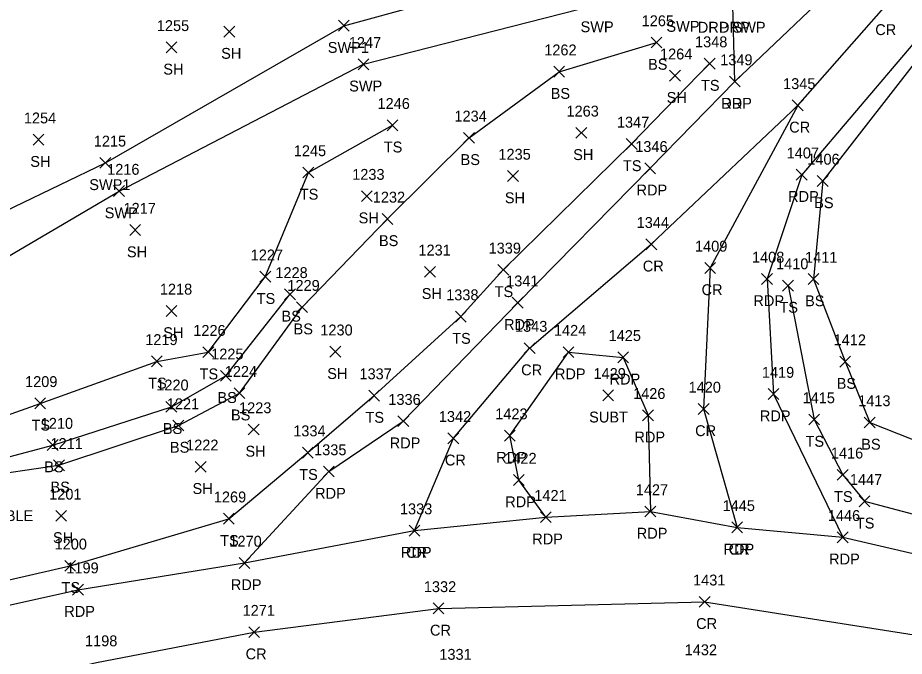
# Model space of a CAD drawing. Extents: x 1586965 to 1590952, y 716317 to 720029.
# Drawn here: x 1587644.2 to 1587807.3, y 719836.9 to 719954.3 of the extents above; entities that cross this region are included whole.
import ezdxf

# ---------------------------------------------------------------- set-up
doc = ezdxf.new("R2010")
doc.units = 0
for name, color, linetype in [('D_C', 7, 'Continuous'), ('L_A', 7, 'Continuous'), ('L_I', 7, 'Continuous'), ('L_TIC', 7, 'Continuous'), ('LELB', 7, 'Continuous'), ('P_A', 7, 'Continuous'), ('P_I', 7, 'Continuous'), ('P_TIC', 7, 'Continuous'), ('PET', 7, 'Continuous'), ('PRC', 7, 'Continuous'), ('R_A', 7, 'Continuous'), ('R_I', 7, 'Continuous'), ('R_TIC', 7, 'Continuous'), ('RDP', 7, 'Continuous'), ('RSW', 7, 'Continuous'), ('U_A', 7, 'Continuous'), ('U_I', 7, 'Continuous'), ('U_TIC', 7, 'Continuous')]:
    doc.layers.add(name, color=color, linetype=linetype)

msp = doc.modelspace()

# ---------------------------------------------------------------- linework, layer by layer
at = {"layer": 'L_TIC'}
for points in [[(1587682.13, 719950.75), (1587684.13, 719952.75)], [(1587684.13, 719950.75), (1587682.13, 719952.75)], [(1587671.48, 719947.85), (1587673.48, 719949.85)], [(1587673.48, 719947.85), (1587671.48, 719949.85)], [(1587760.72, 719948.74), (1587762.72, 719950.74)], [(1587762.72, 719948.74), (1587760.72, 719950.74)], [(1587770.49, 719944.87), (1587772.49, 719946.87)], [(1587772.49, 719944.87), (1587770.49, 719946.87)], [(1587742.8, 719943.38), (1587744.8, 719945.38)], [(1587744.8, 719943.38), (1587742.8, 719945.38)], [(1587764.1, 719942.63), (1587766.1, 719944.63)], [(1587766.1, 719942.63), (1587764.1, 719944.63)], [(1587712.13, 719933.53), (1587714.13, 719935.53)], [(1587714.13, 719933.53), (1587712.13, 719935.53)], [(1587647.01, 719930.87), (1587649.01, 719932.87)], [(1587649.01, 719930.87), (1587647.01, 719932.87)], [(1587726.23, 719931.21), (1587728.23, 719933.21)], [(1587728.23, 719931.21), (1587726.23, 719933.21)], [(1587746.89, 719932.13), (1587748.89, 719934.13)], [(1587748.89, 719932.13), (1587746.89, 719934.13)], [(1587756.13, 719930.09), (1587758.13, 719932.09)], [(1587758.13, 719930.09), (1587756.13, 719932.09)], [(1587696.67, 719924.84), (1587698.67, 719926.84)], [(1587698.67, 719924.84), (1587696.67, 719926.84)], [(1587734.32, 719924.19), (1587736.32, 719926.19)], [(1587736.32, 719924.19), (1587734.32, 719926.19)], [(1587791.29, 719923.28), (1587793.29, 719925.28)], [(1587793.29, 719923.28), (1587791.29, 719925.28)], [(1587707.43, 719920.49), (1587709.43, 719922.49)], [(1587709.43, 719920.49), (1587707.43, 719922.49)], [(1587711.21, 719916.3), (1587713.21, 719918.3)], [(1587713.21, 719916.3), (1587711.21, 719918.3)], [(1587664.79, 719914.25), (1587666.79, 719916.25)], [(1587666.79, 719914.25), (1587664.79, 719916.25)], [(1587719.04, 719906.57), (1587721.04, 719908.57)], [(1587721.04, 719906.57), (1587719.04, 719908.57)], [(1587732.52, 719906.93), (1587734.52, 719908.93)], [(1587734.52, 719906.93), (1587732.52, 719908.93)], [(1587688.74, 719905.67), (1587690.74, 719907.67)], [(1587690.74, 719905.67), (1587688.74, 719907.67)], [(1587789.61, 719905.24), (1587791.61, 719907.24)], [(1587791.61, 719905.24), (1587789.61, 719907.24)], [(1587784.92, 719904.04), (1587786.92, 719906.04)], [(1587786.92, 719904.04), (1587784.92, 719906.04)], [(1587693.28, 719902.42), (1587695.28, 719904.42)], [(1587695.28, 719902.42), (1587693.28, 719904.42)], [(1587695.5, 719900.07), (1587697.5, 719902.07)], [(1587697.5, 719900.07), (1587695.5, 719902.07)], [(1587671.47, 719899.38), (1587673.47, 719901.38)], [(1587673.47, 719899.38), (1587671.47, 719901.38)], [(1587724.71, 719898.33), (1587726.71, 719900.33)], [(1587726.71, 719898.33), (1587724.71, 719900.33)], [(1587678.24, 719891.79), (1587680.24, 719893.79)], [(1587680.24, 719891.79), (1587678.24, 719893.79)], [(1587701.64, 719891.87), (1587703.64, 719893.87)], [(1587703.64, 719891.87), (1587701.64, 719893.87)], [(1587668.78, 719890.1), (1587670.78, 719892.1)], [(1587670.78, 719890.1), (1587668.78, 719892.1)], [(1587795.42, 719890.05), (1587797.42, 719892.05)], [(1587797.42, 719890.05), (1587795.42, 719892.05)], [(1587681.48, 719887.45), (1587683.48, 719889.45)], [(1587683.48, 719887.45), (1587681.48, 719889.45)], [(1587683.98, 719884.25), (1587685.98, 719886.25)], [(1587685.98, 719884.25), (1587683.98, 719886.25)], [(1587708.76, 719883.81), (1587710.76, 719885.81)], [(1587710.76, 719883.81), (1587708.76, 719885.81)], [(1587647.32, 719882.38), (1587649.32, 719884.38)], [(1587649.32, 719882.38), (1587647.32, 719884.38)], [(1587671.46, 719881.75), (1587673.46, 719883.75)], [(1587673.46, 719881.75), (1587671.46, 719883.75)], [(1587789.72, 719879.4), (1587791.72, 719881.4)], [(1587791.72, 719879.4), (1587789.72, 719881.4)], [(1587799.94, 719878.86), (1587801.94, 719880.86)], [(1587801.94, 719878.86), (1587799.94, 719880.86)], [(1587672.75, 719878.3), (1587674.75, 719880.3)], [(1587674.75, 719878.3), (1587672.75, 719880.3)], [(1587686.61, 719877.57), (1587688.61, 719879.57)], [(1587688.61, 719877.57), (1587686.61, 719879.57)], [(1587649.63, 719874.7), (1587651.63, 719876.7)], [(1587651.63, 719874.7), (1587649.63, 719876.7)], [(1587696.57, 719873.31), (1587698.57, 719875.31)], [(1587698.57, 719873.31), (1587696.57, 719875.31)], [(1587650.78, 719870.98), (1587652.78, 719872.98)], [(1587652.78, 719870.98), (1587650.78, 719872.98)], [(1587676.86, 719870.71), (1587678.86, 719872.71)], [(1587678.86, 719870.71), (1587676.86, 719872.71)], [(1587794.97, 719869.23), (1587796.97, 719871.23)], [(1587796.97, 719869.23), (1587794.97, 719871.23)], [(1587798.98, 719864.36), (1587800.98, 719866.36)], [(1587800.98, 719864.36), (1587798.98, 719866.36)], [(1587651.18, 719861.68), (1587653.18, 719863.68)], [(1587653.18, 719861.68), (1587651.18, 719863.68)], [(1587682.02, 719861.16), (1587684.02, 719863.16)], [(1587684.02, 719861.16), (1587682.02, 719863.16)], [(1587652.83, 719852.5), (1587654.83, 719854.5)], [(1587654.83, 719852.5), (1587652.83, 719854.5)]]:
    msp.add_lwpolyline(points, dxfattribs=at)
at = {"layer": 'LELB'}
for points in [[(1587348.34, 719750.32), (1587376.14, 719764.57), (1587411.23, 719784.15), (1587458.35, 719804.18), (1587473.61, 719812.83), (1587489.06, 719812.38), (1587530.46, 719833.31), (1587544.39, 719838.73), (1587578.28, 719845.78), (1587610.35, 719855.43), (1587636.65, 719869.8), (1587651.78, 719871.98), (1587673.75, 719879.3), (1587684.98, 719885.25), (1587696.5, 719901.07), (1587712.21, 719917.3), (1587727.23, 719932.21), (1587743.8, 719944.38), (1587761.72, 719949.74)], [(1587348.34, 719750.32), (1587376.14, 719764.57), (1587411.23, 719784.15), (1587458.35, 719804.18), (1587473.61, 719812.83), (1587489.06, 719812.38), (1587530.46, 719833.31), (1587544.39, 719838.73), (1587578.28, 719845.78), (1587610.35, 719855.43), (1587636.65, 719869.8), (1587651.78, 719871.98), (1587673.75, 719879.3), (1587684.98, 719885.25), (1587696.5, 719901.07), (1587712.21, 719917.3), (1587727.23, 719932.21), (1587743.8, 719944.38), (1587761.72, 719949.74)], [(1587811.93, 719949.52), (1587792.29, 719924.28), (1587790.61, 719906.24), (1587796.42, 719891.05), (1587800.94, 719879.86), (1587824.09, 719870.75), (1587863.89, 719860.75), (1587885.59, 719851.77), (1587915.12, 719838.63), (1587948, 719820.59), (1587984.49, 719804.22), (1588019.19, 719787.78), (1588025.35, 719786.55), (1588029.77, 719787.48), (1588038.8, 719793.55), (1588050.21, 719818.02), (1588057.55, 719835.32), (1588061.37, 719857.52)], [(1587811.93, 719949.52), (1587792.29, 719924.28), (1587790.61, 719906.24), (1587796.42, 719891.05), (1587800.94, 719879.86), (1587824.09, 719870.75), (1587863.89, 719860.75), (1587885.59, 719851.77), (1587915.12, 719838.63), (1587948, 719820.59), (1587984.49, 719804.22), (1588019.19, 719787.78), (1588025.35, 719786.55), (1588029.77, 719787.48), (1588038.8, 719793.55), (1588050.21, 719818.02), (1588057.55, 719835.32), (1588061.37, 719857.52)], [(1587377.37, 719757.84), (1587414.05, 719779.22), (1587461.92, 719797.99), (1587490.32, 719809.23), (1587530.45, 719822.09), (1587580.58, 719835.52), (1587609.69, 719843.39), (1587653.83, 719853.5), (1587683.02, 719862.16), (1587697.57, 719874.31), (1587709.76, 719884.81), (1587725.71, 719899.33), (1587733.52, 719907.93), (1587757.13, 719931.09), (1587771.49, 719945.87)], [(1587377.37, 719757.84), (1587414.05, 719779.22), (1587461.92, 719797.99), (1587490.32, 719809.23), (1587530.45, 719822.09), (1587580.58, 719835.52), (1587609.69, 719843.39), (1587653.83, 719853.5), (1587683.02, 719862.16), (1587697.57, 719874.31), (1587709.76, 719884.81), (1587725.71, 719899.33), (1587733.52, 719907.93), (1587757.13, 719931.09), (1587771.49, 719945.87)], [(1587601.82, 719862.03), (1587606.66, 719869.92), (1587634.17, 719878.33), (1587648.32, 719883.38), (1587669.78, 719891.1), (1587679.24, 719892.79), (1587689.74, 719906.67), (1587697.67, 719925.84), (1587713.13, 719934.53)], [(1587601.82, 719862.03), (1587606.66, 719869.92), (1587634.17, 719878.33), (1587648.32, 719883.38), (1587669.78, 719891.1), (1587679.24, 719892.79), (1587689.74, 719906.67), (1587697.67, 719925.84), (1587713.13, 719934.53)], [(1587785.92, 719905.04), (1587790.72, 719880.4), (1587795.97, 719870.23), (1587799.98, 719865.36), (1587821.67, 719859.64), (1587858.86, 719846.91), (1587879.62, 719839.86), (1587909.63, 719826.79), (1587942.7, 719809.1), (1587978.02, 719791.31), (1588014.84, 719771.38), (1588022.21, 719777.17), (1588033.93, 719779.83), (1588041.77, 719778.33), (1588050.57, 719796.18), (1588059.09, 719817.76), (1588066.51, 719841.34), (1588067.52, 719856.77)], [(1587785.92, 719905.04), (1587790.72, 719880.4), (1587795.97, 719870.23), (1587799.98, 719865.36), (1587821.67, 719859.64), (1587858.86, 719846.91), (1587879.62, 719839.86), (1587909.63, 719826.79), (1587942.7, 719809.1), (1587978.02, 719791.31), (1588014.84, 719771.38), (1588022.21, 719777.17), (1588033.93, 719779.83), (1588041.77, 719778.33), (1588050.57, 719796.18), (1588059.09, 719817.76), (1588066.51, 719841.34), (1588067.52, 719856.77)], [(1587607.33, 719859.31), (1587635.78, 719871.74), (1587650.63, 719875.7), (1587672.46, 719882.75), (1587682.48, 719888.45), (1587694.28, 719903.42)], [(1587607.33, 719859.31), (1587635.78, 719871.74), (1587650.63, 719875.7), (1587672.46, 719882.75), (1587682.48, 719888.45), (1587694.28, 719903.42)]]:
    msp.add_lwpolyline(points, dxfattribs=at)
at = {"layer": 'P_TIC'}
for points in [[(1587775.13, 719941.57), (1587777.13, 719943.57)], [(1587777.13, 719941.57), (1587775.13, 719943.57)], [(1587786.69, 719937.18), (1587788.69, 719939.18)], [(1587788.69, 719937.18), (1587786.69, 719939.18)], [(1587786.69, 719937.18), (1587788.69, 719939.18)], [(1587788.69, 719937.18), (1587786.69, 719939.18)], [(1587759.55, 719925.61), (1587761.55, 719927.61)], [(1587761.55, 719925.61), (1587759.55, 719927.61)], [(1587787.43, 719924.43), (1587789.43, 719926.43)], [(1587789.43, 719924.43), (1587787.43, 719926.43)], [(1587759.76, 719911.63), (1587761.76, 719913.63)], [(1587761.76, 719911.63), (1587759.76, 719913.63)], [(1587770.58, 719907.28), (1587772.58, 719909.28)], [(1587772.58, 719907.28), (1587770.58, 719909.28)], [(1587781.06, 719905.26), (1587783.06, 719907.26)], [(1587783.06, 719905.26), (1587781.06, 719907.26)], [(1587735.18, 719900.89), (1587737.18, 719902.89)], [(1587737.18, 719900.89), (1587735.18, 719902.89)], [(1587737.37, 719892.54), (1587739.37, 719894.54)], [(1587739.37, 719892.54), (1587737.37, 719894.54)], [(1587744.53, 719891.8), (1587746.53, 719893.8)], [(1587746.53, 719891.8), (1587744.53, 719893.8)], [(1587754.59, 719890.84), (1587756.59, 719892.84)], [(1587756.59, 719890.84), (1587754.59, 719892.84)], [(1587782.24, 719884.08), (1587784.24, 719886.08)], [(1587784.24, 719884.08), (1587782.24, 719886.08)], [(1587769.39, 719881.35), (1587771.39, 719883.35)], [(1587771.39, 719881.35), (1587769.39, 719883.35)], [(1587714.13, 719879.1), (1587716.13, 719881.1)], [(1587716.13, 719879.1), (1587714.13, 719881.1)], [(1587759.16, 719880.18), (1587761.16, 719882.18)], [(1587761.16, 719880.18), (1587759.16, 719882.18)], [(1587723.35, 719875.95), (1587725.35, 719877.95)], [(1587725.35, 719875.95), (1587723.35, 719877.95)], [(1587733.73, 719876.44), (1587735.73, 719878.44)], [(1587735.73, 719876.44), (1587733.73, 719878.44)], [(1587700.42, 719869.84), (1587702.42, 719871.84)], [(1587702.42, 719869.84), (1587700.42, 719871.84)], [(1587735.39, 719868.27), (1587737.39, 719870.27)], [(1587737.39, 719868.27), (1587735.39, 719870.27)], [(1587759.59, 719862.49), (1587761.59, 719864.49)], [(1587761.59, 719862.49), (1587759.59, 719864.49)], [(1587759.59, 719862.49), (1587761.59, 719864.49)], [(1587761.59, 719862.49), (1587759.59, 719864.49)], [(1587740.36, 719861.44), (1587742.36, 719863.44)], [(1587742.36, 719861.44), (1587740.36, 719863.44)], [(1587740.36, 719861.44), (1587742.36, 719863.44)], [(1587742.36, 719861.44), (1587740.36, 719863.44)], [(1587775.56, 719859.57), (1587777.56, 719861.57)], [(1587777.56, 719859.57), (1587775.56, 719861.57)], [(1587775.56, 719859.57), (1587777.56, 719861.57)], [(1587777.56, 719859.57), (1587775.56, 719861.57)], [(1587716.2, 719858.97), (1587718.2, 719860.97)], [(1587718.2, 719858.97), (1587716.2, 719860.97)], [(1587716.2, 719858.97), (1587718.2, 719860.97)], [(1587718.2, 719858.97), (1587716.2, 719860.97)], [(1587794.98, 719857.74), (1587796.98, 719859.74)], [(1587796.98, 719857.74), (1587794.98, 719859.74)], [(1587794.98, 719857.74), (1587796.98, 719859.74)], [(1587796.98, 719857.74), (1587794.98, 719859.74)], [(1587684.91, 719853.02), (1587686.91, 719855.02)], [(1587686.91, 719853.02), (1587684.91, 719855.02)], [(1587684.91, 719853.02), (1587686.91, 719855.02)], [(1587686.91, 719853.02), (1587684.91, 719855.02)], [(1587654.26, 719848.11), (1587656.26, 719850.11)], [(1587656.26, 719848.11), (1587654.26, 719850.11)], [(1587720.6, 719844.66), (1587722.6, 719846.66)], [(1587722.6, 719844.66), (1587720.6, 719846.66)], [(1587769.57, 719845.88), (1587771.57, 719847.88)], [(1587771.57, 719845.88), (1587769.57, 719847.88)], [(1587686.69, 719840.3), (1587688.69, 719842.3)], [(1587688.69, 719840.3), (1587686.69, 719842.3)]]:
    msp.add_lwpolyline(points, dxfattribs=at)
at = {"layer": 'PET'}
for points in [[(1587685.91, 719854.02), (1587701.42, 719870.84), (1587715.13, 719880.1), (1587736.18, 719901.89), (1587760.55, 719926.61), (1587776.13, 719942.57), (1587797.01, 719962.52), (1587823.07, 719989.96), (1587838.32, 720006.82)], [(1587852.48, 719995.42), (1587834.78, 719975.99), (1587826.61, 719966.62), (1587809.93, 719950.68), (1587788.43, 719925.43), (1587782.06, 719906.26), (1587783.24, 719885.08), (1587795.98, 719858.74)], [(1587741.36, 719862.44), (1587736.39, 719869.27), (1587734.73, 719877.44), (1587745.53, 719892.8), (1587755.59, 719891.84), (1587760.16, 719881.18), (1587760.59, 719863.49)], [(1587380.68, 719751.95), (1587418.28, 719771.56), (1587465.09, 719790.26), (1587493.56, 719801.4), (1587532.06, 719815.42), (1587581.77, 719830.86), (1587610.56, 719839.15), (1587655.26, 719849.11), (1587685.91, 719854.02), (1587717.2, 719859.97), (1587741.36, 719862.44), (1587760.59, 719863.49), (1587776.56, 719860.57), (1587795.98, 719858.74), (1587820.3, 719853.13)]]:
    msp.add_lwpolyline(points, dxfattribs=at)
at = {"layer": 'PRC'}
for points in [[(1587717.2, 719859.97), (1587724.35, 719876.95), (1587738.37, 719893.54), (1587760.76, 719912.63), (1587787.69, 719938.18), (1587803.53, 719956.11), (1587829.2, 719983.55), (1587845.42, 720001.43)], [(1587717.2, 719859.97), (1587724.35, 719876.95), (1587738.37, 719893.54), (1587760.76, 719912.63), (1587787.69, 719938.18), (1587803.53, 719956.11), (1587829.2, 719983.55), (1587845.42, 720001.43)], [(1587787.69, 719938.18), (1587771.58, 719908.28), (1587770.39, 719882.35), (1587776.56, 719860.57)], [(1587787.69, 719938.18), (1587771.58, 719908.28), (1587770.39, 719882.35), (1587776.56, 719860.57)], [(1587388.91, 719738.13), (1587428.57, 719759.37), (1587470.76, 719777.76), (1587498.92, 719788.92), (1587537.38, 719802.71), (1587585.33, 719817.72), (1587613.69, 719825.22), (1587658.7, 719835.7), (1587687.69, 719841.3), (1587721.6, 719845.66), (1587770.57, 719846.88), (1587822.37, 719838.71)], [(1587388.91, 719738.13), (1587428.57, 719759.37), (1587470.76, 719777.76), (1587498.92, 719788.92), (1587537.38, 719802.71), (1587585.33, 719817.72), (1587613.69, 719825.22), (1587658.7, 719835.7), (1587687.69, 719841.3), (1587721.6, 719845.66), (1587770.57, 719846.88), (1587822.37, 719838.71)]]:
    msp.add_lwpolyline(points, dxfattribs=at)
at = {"layer": 'R_TIC'}
for points in [[(1587703.19, 719951.84), (1587705.19, 719953.84)], [(1587705.19, 719951.84), (1587703.19, 719953.84)], [(1587706.8, 719944.74), (1587708.8, 719946.74)], [(1587708.8, 719944.74), (1587706.8, 719946.74)], [(1587775.13, 719941.57), (1587777.13, 719943.57)], [(1587777.13, 719941.57), (1587775.13, 719943.57)], [(1587659.31, 719926.61), (1587661.31, 719928.61)], [(1587661.31, 719926.61), (1587659.31, 719928.61)], [(1587661.83, 719921.42), (1587663.83, 719923.42)], [(1587663.83, 719921.42), (1587661.83, 719923.42)]]:
    msp.add_lwpolyline(points, dxfattribs=at)
at = {"layer": 'RDP'}
msp.add_lwpolyline([(1587776.13, 719942.57), (1587775.73, 719956.55), (1587774.31, 719963.73), (1587766.54, 719977.43), (1587756.38, 719988.06), (1587741.19, 719994.52), (1587726.17, 719993.52)], dxfattribs=at)
at = {"layer": 'RSW'}
for points in [[(1587502.47, 719906.21), (1587519.59, 719892.17), (1587545.54, 719878.27), (1587571.68, 719875.12), (1587599.39, 719889.75), (1587635.09, 719915.47), (1587660.31, 719927.61), (1587704.19, 719952.84), (1587746.6, 719964.48), (1587765.98, 719964.85), (1587774.31, 719963.73)], [(1587496.93, 719897.46), (1587515.3, 719885.59), (1587544.67, 719871.63), (1587573.67, 719867.5), (1587603.93, 719882.63), (1587638.37, 719908.04), (1587662.83, 719922.42), (1587707.8, 719945.74), (1587750.38, 719956.64), (1587766.18, 719956.72), (1587775.73, 719956.55)]]:
    msp.add_lwpolyline(points, dxfattribs=at)
at = {"layer": 'U_TIC'}
for points in [[(1587751.82, 719883.86), (1587753.82, 719885.86)], [(1587753.82, 719883.86), (1587751.82, 719885.86)]]:
    msp.add_lwpolyline(points, dxfattribs=at)

# ---------------------------------------------------------------- texts
at = {"layer": 'D_C'}
msp.add_text('NO PIPES VISABLE', height=2, dxfattribs=at).set_placement((1587622.52, 719861.72))
at = {"layer": 'L_A'}
for s, p in [('SH', (1587681.62, 719946.75)), ('SH', (1587670.97, 719943.85)), ('BS', (1587760.16, 719944.74)), ('TS', (1587769.9, 719940.87)), ('BS', (1587742.24, 719939.38)), ('SH', (1587763.58, 719938.63)), ('TS', (1587711.54, 719929.53)), ('SH', (1587746.38, 719928.13)), ('SH', (1587646.5, 719926.87)), ('BS', (1587725.67, 719927.21)), ('TS', (1587755.54, 719926.09)), ('TS', (1587696.08, 719920.84)), ('SH', (1587733.81, 719920.19)), ('BS', (1587790.73, 719919.28)), ('SH', (1587706.91, 719916.49)), ('BS', (1587710.65, 719912.3)), ('SH', (1587664.28, 719910.25)), ('TS', (1587688.15, 719901.67)), ('SH', (1587718.52, 719902.57)), ('TS', (1587731.93, 719902.93)), ('TS', (1587784.33, 719900.04)), ('BS', (1587789.05, 719901.24)), ('BS', (1587692.72, 719898.42)), ('SH', (1587670.96, 719895.38)), ('BS', (1587694.94, 719896.07)), ('TS', (1587724.12, 719894.33)), ('TS', (1587677.65, 719887.79)), ('SH', (1587701.13, 719887.87)), ('TS', (1587668.19, 719886.1)), ('BS', (1587794.86, 719886.05)), ('BS', (1587680.92, 719883.45)), ('BS', (1587683.42, 719880.25)), ('TS', (1587708.17, 719879.81)), ('TS', (1587646.73, 719878.38)), ('BS', (1587670.9, 719877.75)), ('TS', (1587789.13, 719875.4)), ('BS', (1587672.19, 719874.3)), ('BS', (1587799.38, 719874.86)), ('SH', (1587686.09, 719873.57)), ('BS', (1587649.07, 719870.7)), ('TS', (1587695.98, 719869.31)), ('BS', (1587650.22, 719866.98)), ('SH', (1587676.35, 719866.71)), ('TS', (1587794.38, 719865.23)), ('TS', (1587798.39, 719860.36)), ('SH', (1587650.67, 719857.68)), ('TS', (1587681.43, 719857.16)), ('TS', (1587652.24, 719848.5))]:
    msp.add_text(s, height=2, dxfattribs=at).set_placement(p)
at = {"layer": 'L_I'}
for s, p in [('1265', (1587758.98, 719952.74)), ('1255', (1587669.78, 719951.85)), ('1348', (1587768.8, 719948.87)), ('1262', (1587741.06, 719947.38)), ('1264', (1587762.36, 719946.63)), ('1246', (1587710.38, 719937.53)), ('1263', (1587745.15, 719936.13)), ('1254', (1587645.32, 719934.87)), ('1234', (1587724.54, 719935.21)), ('1347', (1587754.43, 719934.09)), ('1245', (1587694.98, 719928.84)), ('1235', (1587732.63, 719928.19)), ('1406', (1587789.46, 719927.28)), ('1233', (1587705.73, 719924.49)), ('1232', (1587709.51, 719920.3)), ('1217', (1587663.66, 719918.25)), ('1227', (1587687.05, 719909.67)), ('1231', (1587717.91, 719910.57)), ('1339', (1587730.82, 719910.93)), ('1410', (1587783.71, 719908.04)), ('1411', (1587789.05, 719909.24)), ('1228', (1587691.59, 719906.42)), ('1218', (1587670.34, 719903.38)), ('1229', (1587693.8, 719904.07)), ('1338', (1587723.02, 719902.33)), ('1226', (1587676.49, 719895.79)), ('1230', (1587699.86, 719895.87)), ('1219', (1587667.65, 719894.1)), ('1412', (1587794.3, 719894.05)), ('1225', (1587679.78, 719891.45)), ('1224', (1587682.28, 719888.25)), ('1337', (1587707.06, 719887.81)), ('1209', (1587645.54, 719886.38)), ('1220', (1587669.68, 719885.75)), ('1221', (1587671.62, 719882.3)), ('1415', (1587788.59, 719883.4)), ('1413', (1587798.82, 719882.86)), ('1223', (1587684.91, 719881.57)), ('1210', (1587648.42, 719878.7)), ('1334', (1587694.88, 719877.31)), ('1211', (1587650.22, 719874.98)), ('1222', (1587675.17, 719874.71)), ('1416', (1587793.79, 719873.23)), ('1447', (1587797.29, 719868.36)), ('1201', (1587649.97, 719865.68)), ('1269', (1587680.27, 719865.16)), ('1200', (1587650.97, 719856.5))]:
    msp.add_text(s, height=2, dxfattribs=at).set_placement(p)
at = {"layer": 'P_A'}
for s, p in [('CR', (1587801.96, 719951.11)), ('RDP', (1587773.62, 719937.57)), ('CR', (1587786.13, 719933.18)), ('CR', (1587786.13, 719933.18)), ('RDP', (1587758.04, 719921.61)), ('RDP', (1587785.92, 719920.43)), ('CR', (1587759.19, 719907.63)), ('CR', (1587770.01, 719903.28)), ('RDP', (1587779.54, 719901.26)), ('RDP', (1587733.66, 719896.89)), ('CR', (1587736.81, 719888.54)), ('RDP', (1587743.02, 719887.8)), ('RDP', (1587753.08, 719886.84)), ('RDP', (1587780.73, 719880.08)), ('CR', (1587768.82, 719877.35)), ('RDP', (1587757.65, 719876.18)), ('RDP', (1587712.62, 719875.1)), ('RDP', (1587732.22, 719872.44)), ('CR', (1587722.78, 719871.95)), ('RDP', (1587698.9, 719865.84)), ('RDP', (1587733.88, 719864.27)), ('RDP', (1587738.85, 719857.44)), ('RDP', (1587738.85, 719857.44)), ('RDP', (1587758.08, 719858.49)), ('RDP', (1587758.08, 719858.49)), ('RDP', (1587714.69, 719854.97)), ('CR', (1587715.64, 719854.97)), ('RDP', (1587774.05, 719855.57)), ('CR', (1587774.99, 719855.57)), ('RDP', (1587793.47, 719853.74)), ('RDP', (1587793.47, 719853.74)), ('RDP', (1587683.4, 719849.02)), ('RDP', (1587683.4, 719849.02)), ('RDP', (1587652.75, 719844.11)), ('CR', (1587769, 719841.88)), ('CR', (1587720.04, 719840.66)), ('CR', (1587686.12, 719836.3))]:
    msp.add_text(s, height=2, dxfattribs=at).set_placement(p)
at = {"layer": 'P_I'}
for s, p in [('1349', (1587773.43, 719945.57)), ('1345', (1587785, 719941.18)), ('1345', (1587785, 719941.18)), ('1346', (1587757.8, 719929.61)), ('1407', (1587785.66, 719928.43)), ('1344', (1587758.06, 719915.63)), ('1409', (1587768.8, 719911.28)), ('1408', (1587779.28, 719909.26)), ('1341', (1587734.05, 719904.89)), ('1343', (1587735.68, 719896.54)), ('1424', (1587742.84, 719895.8)), ('1425', (1587752.9, 719894.84)), ('1419', (1587781.1, 719888.08)), ('1420', (1587767.61, 719885.35)), ('1426', (1587757.41, 719884.18)), ('1336', (1587712.38, 719883.1)), ('1423', (1587732.04, 719880.44)), ('1342', (1587721.66, 719879.95)), ('1335', (1587698.72, 719873.84)), ('1422', (1587733.7, 719872.27)), ('1427', (1587757.9, 719866.49)), ('1427', (1587757.9, 719866.49)), ('1421', (1587739.23, 719865.44)), ('1421', (1587739.23, 719865.44)), ('1333', (1587714.51, 719862.97)), ('1333', (1587714.51, 719862.97)), ('1445', (1587773.87, 719863.57)), ('1445', (1587773.87, 719863.57)), ('1446', (1587793.23, 719861.74)), ('1446', (1587793.23, 719861.74)), ('1270', (1587683.13, 719857.02)), ('1270', (1587683.13, 719857.02)), ('1199', (1587653.13, 719852.11)), ('1431', (1587768.44, 719849.88)), ('1332', (1587718.91, 719848.66)), ('1271', (1587685.56, 719844.3)), ('1198', (1587656.57, 719838.7)), ('1331', (1587721.76, 719836.21)), ('1432', (1587766.9, 719837.05))]:
    msp.add_text(s, height=2, dxfattribs=at).set_placement(p)
at = {"layer": 'R_A'}
for s, p in [('SWP', (1587747.74, 719951.64)), ('SWP', (1587763.54, 719951.72)), ('DRP SWP', (1587769.31, 719951.55)), ('DRP', (1587773.22, 719951.55)), ('SWP1', (1587701.23, 719947.84)), ('SWP', (1587705.17, 719940.74)), ('DRP', (1587773.62, 719937.57)), ('SWP1', (1587657.35, 719922.61)), ('SWP', (1587660.19, 719917.42))]:
    msp.add_text(s, height=2, dxfattribs=at).set_placement(p)
at = {"layer": 'R_I'}
for s, p in [('1247', (1587705.11, 719948.74)), ('1349', (1587773.43, 719945.57)), ('1215', (1587658.18, 719930.61)), ('1216', (1587660.64, 719925.42))]:
    msp.add_text(s, height=2, dxfattribs=at).set_placement(p)
at = {"layer": 'U_A'}
msp.add_text('SUBT', height=2, dxfattribs=at).set_placement((1587749.32, 719879.86))
at = {"layer": 'U_I'}
msp.add_text('1429', height=2, dxfattribs=at).set_placement((1587750.12, 719887.86))

doc.saveas('drawing.dxf')
